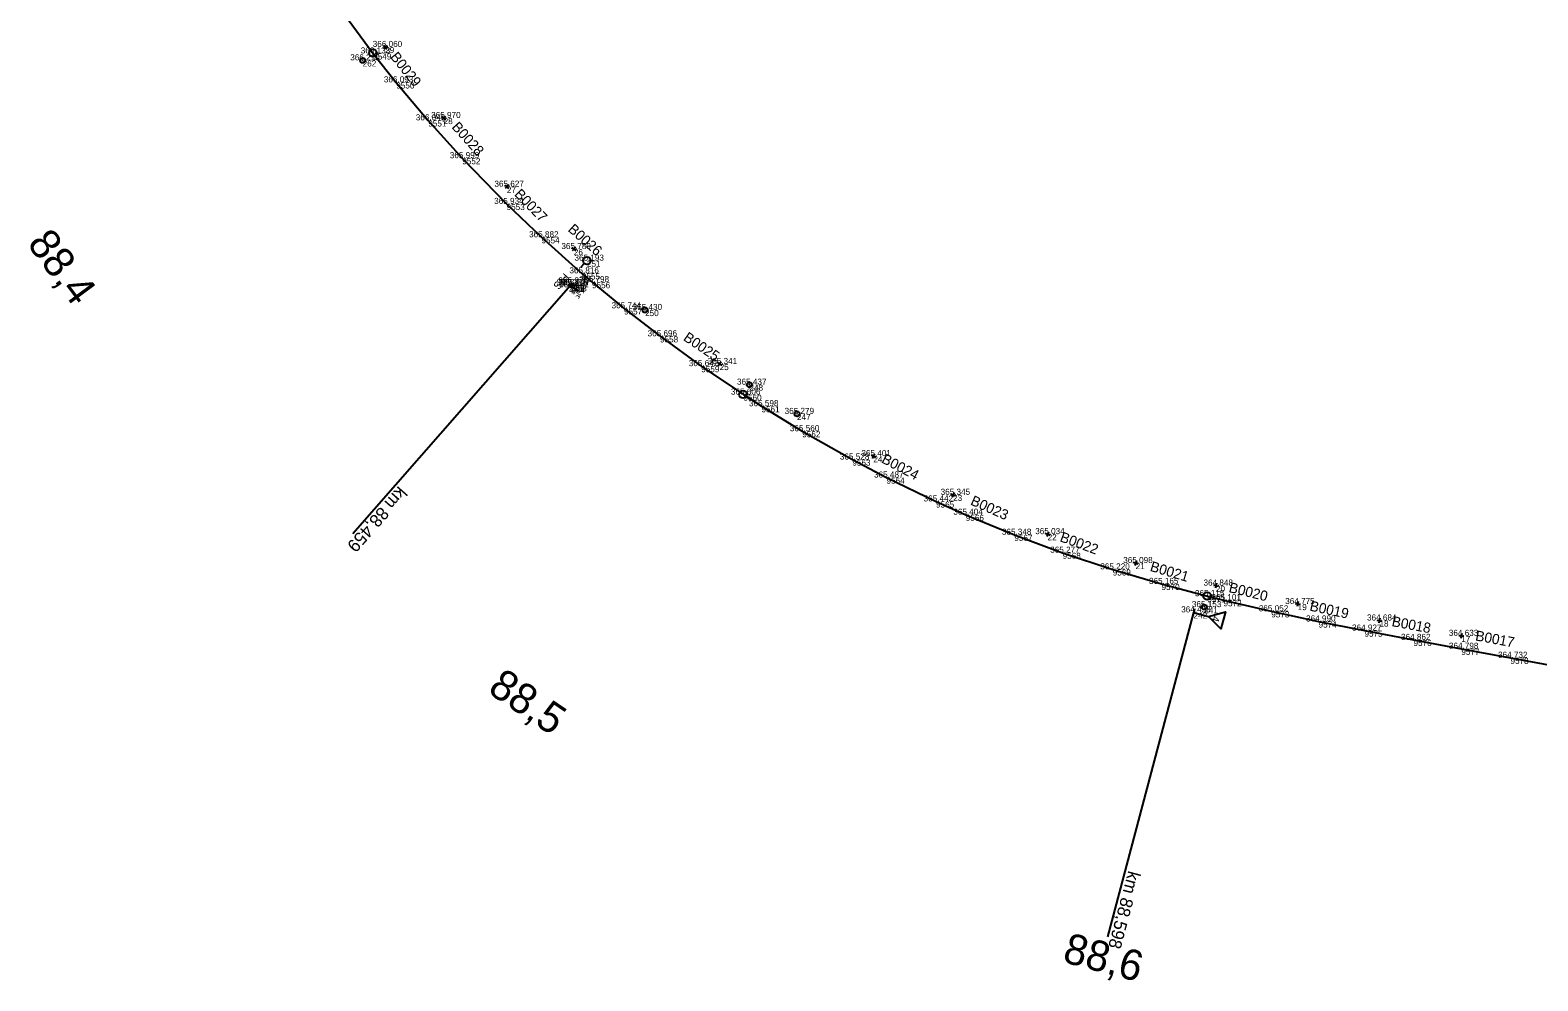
# Model space of a CAD drawing. Extents: x -599511 to -595511, y -1067427 to -1062061.
# Drawn here: x -596220.8 to -595924.1, y -1066614.1 to -1066427 of the extents above; entities that cross this region are included whole.
import ezdxf

# ---------------------------------------------------------------- set-up
doc = ezdxf.new("R2010")
doc.units = 0
for name, color, linetype in [('Vrstva 1', 7, 'Continuous'), ('Vrstva 12', 7, 'Continuous'), ('Vrstva 36', 7, 'Continuous'), ('Vrstva 49', 7, 'Continuous'), ('Vrstva 5', 7, 'Continuous'), ('Vrstva 50', 7, 'Continuous'), ('Vrstva 6', 7, 'Continuous'), ('Vrstva 60', 7, 'Continuous'), ('Vrstva 61', 7, 'Continuous'), ('Vrstva 7', 7, 'Continuous')]:
    doc.layers.add(name, color=color, linetype=linetype)

msp = doc.modelspace()

# ---------------------------------------------------------------- linework, layer by layer
at = {"layer": 'Vrstva 1'}
msp.add_lwpolyline([(-596159.21, -1066423.65), (-596153.33, -1066431.55), (-596148.79, -1066437.25), (-596142.49, -1066444.73), (-596135.81, -1066452.17), (-596127.08, -1066461.18), (-596120.22, -1066467.74), (-596112.27, -1066474.84), (-596110.27, -1066476.56), (-596103.98, -1066481.73), (-596096.89, -1066487.23), (-596088.78, -1066493.1), (-596080.47, -1066498.7), (-596076.92, -1066500.99), (-596068.89, -1066505.91), (-596059.04, -1066511.49), (-596052.32, -1066515.03), (-596042.57, -1066519.73), (-596036.72, -1066522.35), (-596027.16, -1066526.29), (-596017.66, -1066529.82), (-596007.8, -1066533.11), (-595998.21, -1066535.97), (-595989.18, -1066538.38), (-595986.01, -1066539.17), (-595976.61, -1066541.36), (-595967.3, -1066543.36), (-595958.26, -1066545.16), (-595948.62, -1066546.99), (-595939.19, -1066548.73), (-595929.53, -1066550.51), (-595919.87, -1066552.29)], dxfattribs=at)
at = {"layer": 'Vrstva 12'}
msp.add_lwpolyline([(-596114.42, -1066476.81), (-596113.99, -1066477.19), (-596114.39, -1066477.6), (-596114.82, -1066477.21)], close=True, dxfattribs=at)
at = {"layer": 'Vrstva 36'}
msp.add_line((-596111.79, -1066472.9), (-596112.45, -1066473.65), dxfattribs=at)
msp.add_circle((-596111.28, -1066472.34), 0.757, dxfattribs=at)
at = {"layer": 'Vrstva 49'}
for p, q in [((-596114.63, -1066477.16), (-596114.13, -1066477.13)), ((-596114.39, -1066476.89), (-596114.37, -1066477.39))]:
    msp.add_line(p, q, dxfattribs=at)
at = {"layer": 'Vrstva 5'}
for p, q in [((-595991.88, -1066541.57), (-596008.86, -1066605.46)), ((-595991.69, -1066540.85), (-595992.07, -1066542.3))]:
    msp.add_line(p, q, dxfattribs=at)
msp.add_lwpolyline([(-595991.88, -1066541.57), (-595988.98, -1066542.35), (-595985.63, -1066541.43), (-595986.53, -1066544.81), (-595988.98, -1066542.35)], dxfattribs=at)
at = {"layer": 'Vrstva 50'}
for p, q in [((-596099.87, -1066482.02), (-596099.79, -1066482.08)), ((-596069.97, -1066502.49), (-596069.89, -1066502.54))]:
    msp.add_line(p, q, dxfattribs=at)
for centre in [(-596099.83, -1066482.05), (-596069.93, -1066502.51)]:
    msp.add_circle(centre, 0.5, dxfattribs=at)
at = {"layer": 'Vrstva 6'}
for p, q in [((-596114.43, -1066477.18), (-596157.36, -1066526.13)), ((-596114.09, -1066476.81), (-596114.76, -1066477.56)), ((-596112.95, -1066478.5), (-596114.43, -1066477.18))]:
    msp.add_line(p, q, dxfattribs=at)
at = {"layer": 'Vrstva 60'}
for p, q in [((-596150.98, -1066430.28), (-596150.98, -1066430.28)), ((-596155.4, -1066432.92), (-596155.4, -1066432.92)), ((-596153.33, -1066431.55), (-596153.33, -1066431.55)), ((-596148.79, -1066437.25), (-596148.79, -1066437.25)), ((-596142.49, -1066444.73), (-596142.49, -1066444.73)), ((-596139.48, -1066444.26), (-596139.48, -1066444.26)), ((-596135.81, -1066452.17), (-596135.81, -1066452.17)), ((-596127.03, -1066457.79), (-596127.03, -1066457.79)), ((-596127.08, -1066461.18), (-596127.08, -1066461.18)), ((-596120.22, -1066467.74), (-596120.22, -1066467.74)), ((-596113.85, -1066470.06), (-596113.85, -1066470.06)), ((-596112.27, -1066474.84), (-596112.27, -1066474.84)), ((-596111.28, -1066472.34), (-596111.28, -1066472.34)), ((-596114.82, -1066477.21), (-596114.82, -1066477.21)), ((-596114.43, -1066477.18), (-596114.43, -1066477.18)), ((-596114.42, -1066476.81), (-596114.42, -1066476.81)), ((-596114.39, -1066477.6), (-596114.39, -1066477.6)), ((-596114.38, -1066477.14), (-596114.38, -1066477.14)), ((-596113.99, -1066477.19), (-596113.99, -1066477.19)), ((-596110.27, -1066476.56), (-596110.27, -1066476.56)), ((-596103.98, -1066481.73), (-596103.98, -1066481.73)), ((-596099.83, -1066482.05), (-596099.83, -1066482.05)), ((-596096.89, -1066487.23), (-596096.89, -1066487.23)), ((-596085.16, -1066492.68), (-596085.16, -1066492.68)), ((-596088.78, -1066493.1), (-596088.78, -1066493.1)), ((-596079.29, -1066496.75), (-596079.29, -1066496.75)), ((-596080.47, -1066498.7), (-596080.47, -1066498.7)), ((-596076.92, -1066500.99), (-596076.92, -1066500.99)), ((-596069.93, -1066502.51), (-596069.93, -1066502.51)), ((-596068.89, -1066505.91), (-596068.89, -1066505.91)), ((-596059.04, -1066511.49), (-596059.04, -1066511.49)), ((-596054.9, -1066510.81), (-596054.9, -1066510.81)), ((-596052.32, -1066515.03), (-596052.32, -1066515.03)), ((-596039.21, -1066518.43), (-596039.21, -1066518.43)), ((-596042.57, -1066519.73), (-596042.57, -1066519.73)), ((-596036.72, -1066522.35), (-596036.72, -1066522.35)), ((-596027.16, -1066526.29), (-596027.16, -1066526.29)), ((-596020.61, -1066526.17), (-596020.61, -1066526.17)), ((-596017.66, -1066529.82), (-596017.66, -1066529.82)), ((-596007.8, -1066533.11), (-596007.8, -1066533.11)), ((-596003.29, -1066531.86), (-596003.29, -1066531.86)), ((-595998.21, -1066535.97), (-595998.21, -1066535.97)), ((-595987.49, -1066536.3), (-595987.49, -1066536.3)), ((-595989.18, -1066538.38), (-595989.18, -1066538.38)), ((-595986.01, -1066539.17), (-595986.01, -1066539.17)), ((-595971.41, -1066539.93), (-595971.41, -1066539.93)), ((-595991.88, -1066541.57), (-595991.88, -1066541.57)), ((-595989.78, -1066540.53), (-595989.78, -1066540.53)), ((-595976.61, -1066541.36), (-595976.61, -1066541.36)), ((-595967.3, -1066543.36), (-595967.3, -1066543.36)), ((-595958.26, -1066545.16), (-595958.26, -1066545.16)), ((-595955.31, -1066543.17), (-595955.31, -1066543.17)), ((-595948.62, -1066546.99), (-595948.62, -1066546.99)), ((-595939.21, -1066546.19), (-595939.21, -1066546.19)), ((-595939.19, -1066548.73), (-595939.19, -1066548.73)), ((-595929.53, -1066550.51), (-595929.53, -1066550.51))]:
    msp.add_line(p, q, dxfattribs=at)
at = {"layer": 'Vrstva 7'}
for p, q in [((-596150.59, -1066429.97), (-596151.37, -1066430.6)), ((-596151.29, -1066429.89), (-596150.67, -1066430.68)), ((-596155.43, -1066432.88), (-596155.37, -1066432.96)), ((-596139.11, -1066443.93), (-596139.85, -1066444.59)), ((-596139.81, -1066443.89), (-596139.14, -1066444.63)), ((-596126.67, -1066457.44), (-596127.39, -1066458.14)), ((-596127.38, -1066457.43), (-596126.68, -1066458.15)), ((-596114.23, -1066469.73), (-596113.48, -1066470.39)), ((-596113.52, -1066469.69), (-596114.19, -1066470.43)), ((-596085.57, -1066492.4), (-596084.74, -1066492.96)), ((-596084.88, -1066492.27), (-596085.44, -1066493.1)), ((-596079.33, -1066496.72), (-596079.25, -1066496.78)), ((-596054.67, -1066510.37), (-596055.14, -1066511.26)), ((-596055.35, -1066510.58), (-596054.46, -1066511.05)), ((-596039.67, -1066518.23), (-596038.76, -1066518.64)), ((-596039.01, -1066517.98), (-596039.42, -1066518.89)), ((-596021.08, -1066525.99), (-596020.14, -1066526.34)), ((-596020.44, -1066525.7), (-596020.79, -1066526.63)), ((-596003.77, -1066531.71), (-596002.81, -1066532)), ((-596003.15, -1066531.38), (-596003.43, -1066532.34)), ((-595987.97, -1066536.18), (-595987, -1066536.42)), ((-595987.37, -1066535.81), (-595987.61, -1066536.79)), ((-595971.9, -1066539.83), (-595970.92, -1066540.03)), ((-595971.3, -1066539.44), (-595971.51, -1066540.42)), ((-595989.83, -1066540.52), (-595989.73, -1066540.55)), ((-595955.81, -1066543.08), (-595954.82, -1066543.27)), ((-595955.22, -1066542.68), (-595955.41, -1066543.66)), ((-595939.7, -1066546.1), (-595938.72, -1066546.28)), ((-595939.12, -1066545.7), (-595939.3, -1066546.68))]:
    msp.add_line(p, q, dxfattribs=at)
for centre, radius in [((-596155.4, -1066432.92), 0.5), ((-596153.4, -1066431.46), 0.75), ((-596080.56, -1066498.65), 0.75), ((-596079.29, -1066496.75), 0.5), ((-595989.78, -1066540.53), 0.5), ((-595989.22, -1066538.37), 0.75)]:
    msp.add_circle(centre, radius, dxfattribs=at)

# ---------------------------------------------------------------- texts
at = {"layer": 'Vrstva 5'}
for s, height, rotation, p in [('4', 1.5, 255.0619, (-595988.14, -1066542.12)), ('km 88,598', 2.5, 255.1149, (-596004.71, -1066592.3))]:
    msp.add_text(s, height=height, rotation=rotation, dxfattribs=at).set_placement(p)
at = {"layer": 'Vrstva 6'}
for s, height, rotation, p in [('PřS', 1.5, 228.1977, (-596115.76, -1066474.67)), ('  A A ', 1, 318.1977, (-596115.09, -1066477.93)), ('km 88,459', 2.5, 228.743, (-596148.34, -1066516.57))]:
    msp.add_text(s, height=height, rotation=rotation, dxfattribs=at).set_placement(p)
at = {"layer": 'Vrstva 60'}
for s, p in [('29', (-596150.98, -1066431.48)), ('262', (-596155.4, -1066434.12)), ('9549', (-596153.33, -1066432.75)), ('9550', (-596148.79, -1066438.45)), ('9551', (-596142.49, -1066445.93)), ('28', (-596139.48, -1066445.46)), ('9552', (-596135.81, -1066453.37)), ('27', (-596127.03, -1066458.99)), ('9553', (-596127.08, -1066462.38)), ('9554', (-596120.22, -1066468.94)), ('26', (-596113.85, -1066471.26)), ('9555', (-596112.27, -1066476.04)), ('251', (-596111.28, -1066473.54)), ('255', (-596114.82, -1066478.41)), ('256', (-596114.42, -1066478.01)), ('257', (-596114.43, -1066478.38)), ('254', (-596114.39, -1066478.8)), ('258', (-596114.38, -1066478.34)), ('253', (-596113.99, -1066478.39)), ('9556', (-596110.27, -1066477.76)), ('9557', (-596103.98, -1066482.93)), ('250', (-596099.83, -1066483.25)), ('9558', (-596096.89, -1066488.43)), ('25', (-596085.16, -1066493.88)), ('9559', (-596088.78, -1066494.3)), ('248', (-596079.29, -1066497.95)), ('9560', (-596080.47, -1066499.9)), ('9561', (-596076.92, -1066502.19)), ('247', (-596069.93, -1066503.71)), ('9562', (-596068.89, -1066507.11)), ('9563', (-596059.04, -1066512.69)), ('24', (-596054.9, -1066512.01)), ('9564', (-596052.32, -1066516.23)), ('23', (-596039.21, -1066519.63)), ('9565', (-596042.57, -1066520.93)), ('9566', (-596036.72, -1066523.55)), ('9567', (-596027.16, -1066527.49)), ('22', (-596020.61, -1066527.37)), ('9568', (-596017.66, -1066531.02)), ('9569', (-596007.8, -1066534.31)), ('21', (-596003.29, -1066533.06)), ('9570', (-595998.21, -1066537.17)), ('20', (-595987.49, -1066537.5)), ('9571', (-595989.18, -1066539.58)), ('9572', (-595986.01, -1066540.37)), ('19', (-595971.41, -1066541.13)), ('242', (-595991.88, -1066542.77)), ('241', (-595989.78, -1066541.73)), ('9573', (-595976.61, -1066542.56)), ('9574', (-595967.3, -1066544.56)), ('9575', (-595958.26, -1066546.36)), ('18', (-595955.31, -1066544.37)), ('9576', (-595948.62, -1066548.19)), ('9577', (-595939.19, -1066549.93)), ('17', (-595939.21, -1066547.39)), ('9578', (-595929.53, -1066551.71))]:
    msp.add_text(s, height=1.2, dxfattribs=at).set_placement(p)
at = {"layer": 'Vrstva 61'}
for s, p in [('366.133', (-596155.78, -1066431.55)), ('366.060', (-596153.43, -1066430.28)), ('366.210', (-596157.85, -1066432.92)), ('366.093', (-596151.24, -1066437.25)), ('366.046', (-596144.95, -1066444.73)), ('365.970', (-596141.93, -1066444.26)), ('365.999', (-596138.26, -1066452.17)), ('365.627', (-596129.48, -1066457.79)), ('365.934', (-596129.53, -1066461.18)), ('365.882', (-596122.66, -1066467.74)), ('365.780', (-596116.3, -1066470.06)), ('365.193', (-596113.73, -1066472.34)), ('365.816', (-596114.72, -1066474.84)), ('365.267', (-596117.27, -1066477.21)), ('365.278', (-596116.88, -1066477.18)), ('365.275', (-596116.88, -1066476.81)), ('365.279', (-596116.83, -1066477.14)), ('365.271', (-596116.75, -1066477.6)), ('365.277', (-596116.44, -1066477.19)), ('365.798', (-596112.72, -1066476.56)), ('365.744', (-596106.43, -1066481.73)), ('365.430', (-596102.28, -1066482.05)), ('365.696', (-596099.34, -1066487.23)), ('365.642', (-596091.23, -1066493.1)), ('365.341', (-596087.51, -1066492.68)), ('365.437', (-596081.74, -1066496.75)), ('365.606', (-596082.93, -1066498.7)), ('365.598', (-596079.38, -1066500.99)), ('365.279', (-596072.38, -1066502.51)), ('365.560', (-596071.34, -1066505.91)), ('365.528', (-596061.5, -1066511.49)), ('365.401', (-596057.26, -1066510.81)), ('365.487', (-596054.77, -1066515.03)), ('365.442', (-596045.02, -1066519.73)), ('365.345', (-596041.67, -1066518.43)), ('365.404', (-596039.17, -1066522.35)), ('365.348', (-596029.61, -1066526.29)), ('365.034', (-596023.06, -1066526.17)), ('365.277', (-596020.11, -1066529.82)), ('365.098', (-596005.74, -1066531.86)), ('365.220', (-596010.25, -1066533.11)), ('365.165', (-596000.67, -1066535.97)), ('365.115', (-595991.63, -1066538.38)), ('364.848', (-595989.94, -1066536.3)), ('365.153', (-595992.23, -1066540.53)), ('365.101', (-595988.37, -1066539.17)), ('365.052', (-595979.06, -1066541.36)), ('364.775', (-595973.86, -1066539.93)), ('364.453', (-595994.33, -1066541.57)), ('364.990', (-595969.75, -1066543.36)), ('364.684', (-595957.76, -1066543.17)), ('364.927', (-595960.71, -1066545.16)), ('364.862', (-595951.07, -1066546.99)), ('364.633', (-595941.66, -1066546.19)), ('364.798', (-595941.64, -1066548.73)), ('364.732', (-595931.98, -1066550.51))]:
    msp.add_text(s, height=1.2, dxfattribs=at).set_placement(p)
at = {"layer": 'Vrstva 7'}
for s, height, rotation, p in [('B0029', 2, 308.5235, (-596150.09, -1066432.25)), ('B0028', 2, 311.9361, (-596138.01, -1066446.11)), ('B0027', 2, 314.1216, (-596125.69, -1066459.37)), ('B0026', 2, 318.1977, (-596115.15, -1066466.39)), ('88,4', 6, 306.6443, (-596221.58, -1066469.03)), ('B0025', 2, 325.9911, (-596092.46, -1066487.9)), ('B0024', 2, 332.2545, (-596053.46, -1066512)), ('B0023', 2, 335.8913, (-596035.95, -1066520.3)), ('B0022', 2, 339.622, (-596018.35, -1066527.53)), ('B0021', 2, 343.4083, (-596000.6, -1066533.37)), ('B0020', 2, 346.0276, (-595985.09, -1066537.54)), ('B0019', 2, 347.9128, (-595969.17, -1066541.2)), ('B0018', 2, 349.2551, (-595953.01, -1066544.25)), ('B0017', 2, 349.5536, (-595936.55, -1066547.07)), ('88,5', 6, 325.9911, (-596131.03, -1066557.23)), ('88,6', 6, 345.0619, (-596017.89, -1066610.32))]:
    msp.add_text(s, height=height, rotation=rotation, dxfattribs=at).set_placement(p)

doc.saveas('drawing.dxf')
